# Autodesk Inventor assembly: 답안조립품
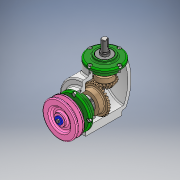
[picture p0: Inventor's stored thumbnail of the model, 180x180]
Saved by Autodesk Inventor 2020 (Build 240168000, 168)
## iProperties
Created: 2023-12
Part Number: 답안조립품
Document SubType Name: Weldment
Designer: 1강의실14
Weld Material: Welded Aluminum-6061
Author: 1강의실14
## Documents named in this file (17)
- C:\Users\1강의실14\Downloads\731203V1002\답안조립품.iam
- C:\Users\1강의실14\Downloads\731203V1002\본체.ipt
- C:\Users\1강의실14\Downloads\731203V1002\커버.ipt
- C:\Users\1강의실14\Downloads\731203V1002\베어링 6203.ipt
- C:\Users\1강의실14\Downloads\731203V1002\메인 축.ipt
- 메인 축.ipt
- C:\Users\1강의실14\Downloads\731203V1002\서브 축.ipt
- 서브 축.ipt
- C:\Users\1강의실14\Downloads\731203V1002\오일실 17 x 32 x 8.ipt
- C:\Users\1강의실14\Downloads\731203V1002\키 5 x 5 x 14.ipt
- C:\Users\1강의실14\Downloads\731203V1002\키 4 x 4 x 14.ipt
- C:\Users\1강의실14\Downloads\731203V1002\메인 베벨기어.ipt
- C:\Users\1강의실14\Downloads\731203V1002\서브 베벨기어.ipt
- C:\Users\1강의실14\Downloads\731203V1002\볼트 M4 x 10.ipt
- C:\Users\1강의실14\Downloads\731203V1002\V-벨트풀리.ipt
- C:\Users\1강의실14\Downloads\731203V1002\와셔 4 x 16.ipt
- C:\Users\1강의실14\Downloads\731203V1002\육각볼트 M4 x 8.ipt
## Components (1 placed, 1 different names)
1. V-벨트풀리:1
